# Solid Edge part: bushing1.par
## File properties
Title: Bushing
Author: Deepak Maini
Template: normal.par
Last saved by: Robert a Rhodes jr
Revision: 3
Application: Solid Edge
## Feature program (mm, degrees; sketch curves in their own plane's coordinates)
sketch for "unnamed RevolvedProtrusion 1" plane through (0, 0, -8.3976) normal (0, 0, 1) x-axis (1, 0, 0)
  line (-23.1281, 31.75) -> (-23.1281, 34.9556)
  line (-23.1281, 34.9556) -> (-38.3879, 34.9556)
  line (-38.3879, 34.9556) -> (-38.3879, 31.75)
  line (-38.3879, 31.75) -> (-23.1281, 31.75)
revolve "unnamed RevolvedProtrusion 1" add full turn 360 deg about sketch line (-48.5775, 25.4) -> (54.7954, 25.4)
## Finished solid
Body 1: solid body, 4 faces, 4 edges, 0 vertices.
  Faces by surface: cylinder 2, plane 2
  Edges by curve: circle 4
Bounding box of the edges (mm): 15.260 x 19.111 x 19.111, from (-38.3879, 15.8444, -17.9532) to (-23.1281, 34.9556, 1.1579).
Cylindrical faces by radius (mm): R6.35 x1, R9.5556 x1
Planar faces by outward normal: +x 1, -x 1
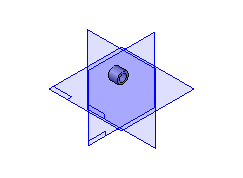
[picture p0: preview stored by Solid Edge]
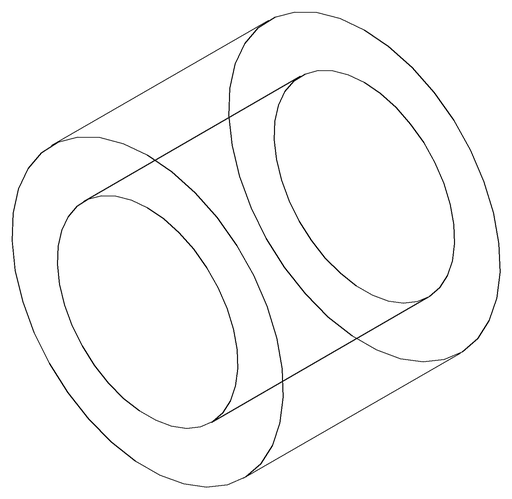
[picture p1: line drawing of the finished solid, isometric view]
